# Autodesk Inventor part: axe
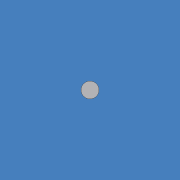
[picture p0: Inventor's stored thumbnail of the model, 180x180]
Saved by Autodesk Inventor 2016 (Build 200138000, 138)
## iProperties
Shininess: 64.0
Length Units: 11269
Angle Units: 11279
Time Units: 11290
Mass Units: 11283
Length Display Precision: 3
Angle Display Precision: 2
Compacted: True
Part Number: axe
Document SubType Name: Modeling
Created: 2003-07
Material: Générique
Designer: trameau
Density: 1 g/cm^3
Appearance: Par défaut
Density: 0.0
Volumn: 0.0
Area: 0.0
PropertySet Name: Model Information
Control State: 0
Master: False
Checked Out: False
Author: trameau
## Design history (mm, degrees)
sketch "Esquisse1"
  geometry: C1 r 5 at (0, 0)
  constraints: 1 centre point
  dimensions: "d0" = 10 dimension on C1.centre C1; "d0" = 10 diameter of C1
extrude "Extrusion1" new body sketch "Esquisse1" distance "d1" = 30; taper "d2" = 0 deg
node "Solide1"
node "Corps solides"
node "Corps surfaciques"
